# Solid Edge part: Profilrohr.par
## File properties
Username: bmolnar
Dokumentum tartalom típus: 0
Author: bmolnar
Last saved by: bmolnar
Revision: 96
Sűrűség: 0,000 kg/m^3
Pontosság: 0,990
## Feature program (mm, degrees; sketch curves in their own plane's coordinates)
base feature "unnamed BaseFeature 1"
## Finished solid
Body 1: solid body, 95 faces, 278 edges, 184 vertices.
  Faces by surface: plane 48, cylinder 47
  Edges by curve: line 184, circle 94
Bounding box of the edges (mm): 65.500 x 65.500 x 336.000, from (-32.75, -32.75, 0) to (32.75, 32.75, 336).
Cylindrical faces by radius (mm): R0.15 x20, R0.25 x20, R6.5 x2, R8 x4, R25 x1
Planar faces by outward normal: +x 11, +y 12, +z 1, -x 11, -y 12, -z 1
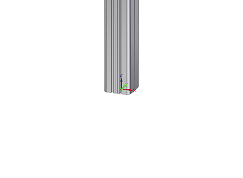
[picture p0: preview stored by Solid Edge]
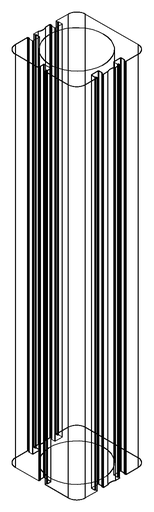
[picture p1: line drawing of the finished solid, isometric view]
